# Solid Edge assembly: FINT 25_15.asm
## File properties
Title: Zylinder
Author: bmolnar
Template: iso assembly.asm
Last saved by: bmolnar
Revision: 11
Application: Solid Edge
Username: bmolnar
Dokumentum tartalom típus: 1
Document Number: FINT 25/15
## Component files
Kit_2.par
Profilrohr.par
Platte.par
hrungsstange.par
Kolbenstange.par
Kit_1.par
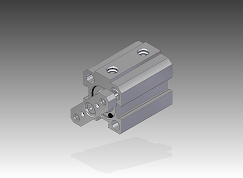
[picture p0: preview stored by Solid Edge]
